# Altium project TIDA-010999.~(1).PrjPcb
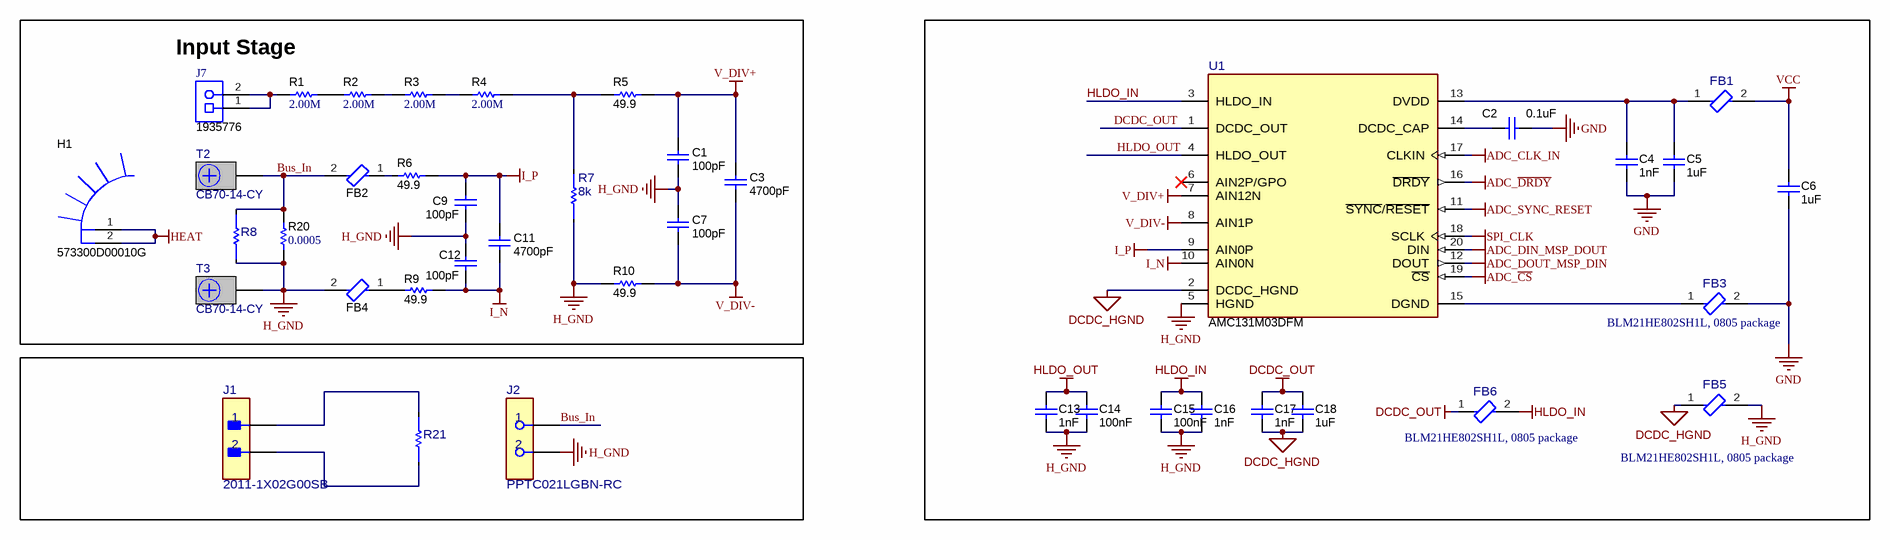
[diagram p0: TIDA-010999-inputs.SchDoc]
CopyrightYear: 2018; PCB_Layout: Who did the Layout?; PCB_Rev: E1; PRJ_Customer: Public Release; PRJ_Engineer: Enter name of project lead; PRJ_Number: XXX###; PRJ_Title: Change in menu Project|Project Options|Parameters; SCH_Rev: E1; TechSupport: http://www.ti.com/support; TID: N/A
3 sheets, 93 parts. Net scope: global (net labels, ports and power ports of the same name join across sheets).
Board file: TIDA-010999.PcbDoc
Sheets:
  TIDA-010999-inputs.SchDoc
  TIDA-010999_Hardware.SchDoc
  Sheet2.SchDoc

## Sheet TIDA-010999-inputs.SchDoc
size 431 x 279 mm; Date: Not shown in title block; ApprovedBy: Not shown in title block; CheckedBy: Not shown in title block; Author: Not shown in title block; CompanyName: Not shown in title block; Engineer: Not shown in title block; Organization: Not shown in title block; Address1: Not shown in title block; Address2: Not shown in title block; Address3: Not shown in title block; Address4: Not shown in title block; DocumentNumber: 2; Revision: Use project parameter SCH_Rev; SheetNumber: 1; SheetTotal: 2; PageSetup: Record=PageOptions¦CenterHorizontal=True¦CenterVertical=True¦PrintScale=1.00¦XCorrection=1.00¦YCorrection=1.00¦PrintKind=0¦BorderSize=5000000¦LeftOffset=0¦BottomOffset=0¦Orientation=2¦PaperLength=1000¦PaperWidth=1000¦Scale=100¦PaperSource=15¦PrintQuality=600¦MediaType=1¦DitherType=10¦PaperKind=Letter¦PrintScaleMode=1

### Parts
C1  ValueDisplayed: 100pF  [0603]  (hidden comment: 885012006057)
C2  value 0.1uF  [0603]  (hidden comment: C1608X7R1H104K080AA)
C3  ValueDisplayed: 4700pF  [0603]  (hidden comment: C0603C472J1GAC7867)
C4  Cap_F: 1nF  [0603]  (hidden comment: C0603C102K5RACTU)
C5  ValueDisplayed: 1uF  [0603]  (hidden comment: C0603C105K3RACTU)
C6  ValueDisplayed: 1uF  [0603]  (hidden comment: C0603C105K3RACTU)
C7  ValueDisplayed: 100pF  [0603]  (hidden comment: 885012006057)
C9  ValueDisplayed: 100pF  [0603]  (hidden comment: 885012006057)
C11  ValueDisplayed: 4700pF  [0603]  (hidden comment: C0603C472J1GAC7867)
C12  ValueDisplayed: 100pF  [0603]  (hidden comment: 885012006057)
C13  Cap_F: 1nF  [0603]  (hidden comment: C0603C102K5RACTU)
C14  Cap_F: 100nF  [0603]  (hidden comment: C1608X7R1H104K080AA)
C15  Cap_F: 100nF  [0603]  (hidden comment: C1608X7R1H104K080AA)
C16  Cap_F: 1nF  [0603]  (hidden comment: C0603C102K5RACTU)
C17  Cap_F: 1nF  [0603]  (hidden comment: C0603C102K5RACTU)
C18  ValueDisplayed: 1uF  [0603]  (hidden comment: C0603C105K3RACTU)
FB1  BLM21HE472SH1L  [FP-BLM21HE472SH1L_0805-MFG]  (value not drawn)
FB2  74269244182  [FP-74269244182_0402-MFG]  (value not drawn)
FB3  BLM21HE472SH1L  [FP-BLM21HE472SH1L_0805-MFG]  (value not drawn)
FB4  74269244182  [FP-74269244182_0402-MFG]  (value not drawn)
FB5  BLM21HE472SH1L  [FP-BLM21HE472SH1L_0805-MFG]  (value not drawn)
FB6  BLM21HE472SH1L  [FP-BLM21HE472SH1L_0805-MFG]  (value not drawn)
H1  573300D00010G  [HEATSINK_573300D00010G]
J1  2011-1X02G00SB  [FP-2011-1X02G00SB_HDR-MFG]
J2  PPTC021LGBN-RC  [FP-PPTC021LGBN-RC_CONN_HDR2-MFG]
J7  1935776  [Phoenix_1935776]
R1  ValueDisplayed: 2.00M  [TNPV1206]  (hidden comment: TNPV12062M00BEEN)
R2  ValueDisplayed: 2.00M  [TNPV1206]  (hidden comment: TNPV12062M00BEEN)
R3  ValueDisplayed: 2.00M  [TNPV1206]  (hidden comment: TNPV12062M00BEEN)
R4  ValueDisplayed: 2.00M  [TNPV1206]  (hidden comment: TNPV12062M00BEEN)
R5  ValueDisplayed: 49.9  [0603]  (hidden comment: CRCW060349R9FKEA)
R6  ValueDisplayed: 49.9  [0603]  (hidden comment: CRCW060349R9FKEA)
R7  8k  [FP-RT0603BRE078KL_0603-MFG]
R8  EBWM2512F1L00S9  [FP-EBWM2512F1L00S9_2512-MFG]  (value not drawn)
R9  ValueDisplayed: 49.9  [0603]  (hidden comment: CRCW060349R9FKEA)
R10  ValueDisplayed: 49.9  [0603]  (hidden comment: CRCW060349R9FKEA)
R20  ValueDisplayed: 0.0005  [WSLF2512L5000]  (hidden comment: WSLF2512L5000FEA)
R21  SBZ-8420-CM2-R00005  [FP-SBZ-8420-CM2-R00005_8420-MFG]  (value not drawn)
T2  CB70-14-CY  [CB70-14-CY]
T3  CB70-14-CY  [CB70-14-CY]
U1  AMC131M03DFM  [DFM0020A-MFG]

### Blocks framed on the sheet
Input Stage: C1 C3 C7 C9 C11 C12 FB2 FB4 H1 J7 R1-R10 R20 T2 T3

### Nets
ADC_~{CS}: U1.19(~{CS})
ADC_CLK_IN: U1.17(CLKIN)
ADC_~{DRDY}: U1.16(~{DRDY})
ADC_DIN_MSP_DOUT: U1.20(DIN)
ADC_DOUT_MSP_DIN: U1.12(DOUT)
ADC_SYNC_RESET: U1.11(~{SYNC}/~{RESET})
DCDC_HGND: C17.2 C18.1 FB5.1 U1.2(DCDC_HGND)
DCDC_OUT: C17.1 C18.2 FB6.1 U1.1(DCDC_OUT)
GND: C2.2 C4.2 C5.1 C6.1 FB3.2
H_GND: C1.2 C7.1 C9.2 C12.1 C13.2 C14.2 C15.2 C16.2 FB4.2 FB5.2 J2.2 R7.1 R8.1 R10.1 R20.1 T3.1 U1.5(HGND)
HEAT: H1.1 H1.2
HLDO_IN: C15.1 C16.1 FB6.2 U1.3(HLDO_IN)
HLDO_OUT: C13.1 C14.1 U1.4(HLDO_OUT)
I_N: C11.2 C12.2 R9.2 U1.10(AIN0N)
I_P: C9.1 C11.1 R6.2 U1.9(AIN0P)
SPI_CLK: U1.18(SCLK)
V_DIV+: C1.1 C3.1 R5.2 U1.7(AIN12N)
V_DIV-: C3.2 C7.2 R10.2 U1.8(AIN1P)
VCC: C6.2 FB1.2
Bus_In: FB2.2 J2.1 R8.2 R20.2 T2.1
NetC2_1: C2.1 U1.14(DCDC_CAP)
NetC4_1: C4.1 C5.2 FB1.1 U1.13(DVDD)
NetFB2_1: FB2.1 R6.1
NetFB3_1: FB3.1 U1.15(DGND)
NetFB4_1: FB4.1 R9.1
NetJ1_1: J1.1 R21.2
NetJ1_2: J1.2 R21.1
NetJ7_1: J7.1 J7.2 R1.1
NetR1_2: R1.2 R2.1
NetR2_2: R2.2 R3.1
NetR3_2: R3.2 R4.1
NetR4_2: R4.2 R5.1 R7.2

Not connected (* = marked no-connect by the designer): U1 6(AIN2P/GPO)*

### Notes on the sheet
- (near FB3) BLM21HE802SH1L, 0805 package
- (near FB6) BLM21HE802SH1L, 0805 package
- (near FB5) BLM21HE802SH1L, 0805 package

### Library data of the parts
C1 C7 C9 C12 = CMP-0006822-4: CAP, CERM, 100 pF, 50 V, +/- 5%, C0G/NP0, 0603; Manufacturer: Wurth Elektronik; TaMin_C: -55°C; Polarized: N; SizeAreaWB_mm2: 4.68; Value1: Unknown; U/M: EA; Value: 100pF; TaMax_C: 125°C; SizeZ_mm: 1; SizeX_mm: 1.6; SizeY_mm: 0.8; Value2: 50V; SizeArea_mm2: 1.28; AEC Category: Q200
C2 = CMP-0007044-5: CAP, CERM, 0.1 uF, 50 V, +/- 10%, X7R, 0603; Manufacturer: TDK; TaMin_C: -55°C; ESR_ohm: 29.6m; Polarized: N; SizeAreaWB_mm2: 4.68; Value1: 0.0296 ohm; U/M: EA; TaMax_C: 125°C; SizeZ_mm: 1; SizeX_mm: 1.6; SizeY_mm: 0.8; Value2: 50V; SizeArea_mm2: 1.28; IRMS_A: 971.99mA; AEC Category: Q200
C3 C11 = CMP-0006941-4: CAP, CERM, 4700 pF, 100 V, +/- 5%, C0G/NP0, 0603; Manufacturer: Kemet; TaMin_C: -55°C; Polarized: N; SizeAreaWB_mm2: 4.68; Value1: Unknown; U/M: EA; Value: 4700pF; TaMax_C: 125°C; SizeZ_mm: 1; SizeX_mm: 1.6; SizeY_mm: 0.8; Value2: 100V; SizeArea_mm2: 1.28; Cap_F: 4.7nF; AEC Category: Q200
C4 C13 C16 C17 = CMP-0006847-4: CAP, CERM, 1000 pF, 50 V, +/- 10%, X7R, 0603; Manufacturer: Kemet; TaMin_C: -55°C; Polarized: N; SizeAreaWB_mm2: 4.68; Value1: Unknown; U/M: EA; Value: 1000pF; TaMax_C: 125°C; SizeZ_mm: 1; SizeX_mm: 1.6; SizeY_mm: 0.8; Value2: 50V; SizeArea_mm2: 1.28; AEC Category: Q200
C5 C6 C18 = CMP-0006867-4: CAP, CERM, 1 uF, 25 V, +/- 10%, X7R, 0603; Manufacturer: Kemet; TaMin_C: -55°C; Polarized: N; SizeAreaWB_mm2: 4.68; Value1: Unknown; U/M: EA; Value: 1uF; TaMax_C: 125°C; SizeZ_mm: 1; SizeX_mm: 1.6; SizeY_mm: 0.8; Value2: 25V; SizeArea_mm2: 1.28; CompType: Capacitor; Cap_F: 1µF; AEC Category: Q200
C14 C15 = CMP-0007044-5: CAP, CERM, 0.1 uF, 50 V, +/- 10%, X7R, 0603; Manufacturer: TDK; TaMin_C: -55°C; ESR_ohm: 29.6m; Polarized: N; SizeAreaWB_mm2: 4.68; Value1: 0.0296 ohm; U/M: EA; Value: 0.1uF; TaMax_C: 125°C; SizeZ_mm: 1; SizeX_mm: 1.6; SizeY_mm: 0.8; Value2: 50V; SizeArea_mm2: 1.28; IRMS_A: 971.99mA; AEC Category: Q200
FB1 FB3 FB5 FB6 = CMP-0037616-1: 4.7 kOhms @ 100 MHz 1 Signal Line Ferrite Bead 0805 (2012 Metric) 850mA 400mOhm; Manufacturer: Murata; DCR_ohm: 0.4; SizeZ_mm: 1.45mm; AEC Grade: Grade 1; AEC Qualified: Yes; Impedance At Frequency: 4700Ω @ 100MHz
FB2 FB4 = CMP-0091663-1: 1.8 kOhms @ 100MHz 1 Power, Signal Line Ferrite Bead 0402 (1005 Metric) 210mA 2.1Ohm; Manufacturer: Wurth Electronics; SizeZ_mm: 0.55mm; AEC Qualified: No; DCR_ohm: 2.1; Tolerance_%: 25%; Test Frequency: 1GHz; Impedance At Frequency: 1800Ω @ 100MHz
H1 = CMP-0004011-1: Heatsink, DDPAK/TO-263, SMT; Manufacturer: Aavid
J1 = CMP-0092598-1: Connector Header Through Hole 2 position 0.100" (2.54mm); Manufacturer: Oupiin; Row_Count: 1; SizeZ_mm: 9.1mm; Conn Orientation: Straight; AEC Qualified: No; Current_A: 3A; ContactFinish: Gold,Nickel; Conn Gender: Male; Voltage_V: 150V
J2 = CMP-0122186-1: 2 Position Header Connector 0.100" (2.54mm) Through Hole, Right Angle Tin; Manufacturer: Sullins; ContactFinish: Tin,Nickel; Current_A: 3A; Row_Count: 1; Voltage_V: 250V; AEC Qualified: No; Conn Gender: Female; Is Female: yes; SizeZ_mm: 2.74mm
J7 = CMP-0055506-1: Terminal Block, 2x1, 5mm, Green, TH; Manufacturer: Phoenix Contact; CNHeader: FALSE; Green_Lifecycle: Not Set; Gender: Female; Green_REACh: Incomplete; Row_Count: 1; Pitch_mm: 5; CT: TRUE
R1-R4 = CMP-0018810-2: RES, 2.00 M, 0.1%, 1 W, 1206; Manufacturer: Vishay Draloric; Power_W: 1W; TempCo: 25 ppm/C; Value_Code: 2M00; U/M: EA; Value: 2.00Meg; EIA_Code: E192; Res_ohm: 2M; SizeX_mm: 3.2; SizeY_mm: 1.6; SizeZ_mm: 0.65; SizeArea_mm2: 5.12; AEC Qualified: N; VDC_V: 700V; AEC Category: Q200
R5 R10 = CMP-0022448-2: RES, 49.9, 1%, 0.1 W, 0603; Manufacturer: Vishay-Dale; Power_W: 100mW; TempCo: 100 ppm/C; Value_Code: 49R9; U/M: EA; Value: 49.9; EIA_Code: E96; SizeX_mm: 1.6; SizeY_mm: 0.8; SizeZ_mm: 1; Value2: 0.1W; SizeArea_mm2: 1.28; VDC_V: 75V; AEC Category: Q200
R6 R9 = CMP-0022448-4: RES, 49.9, 1%, 0.1 W, AEC-Q200 Grade 0, 0603; Manufacturer: Vishay-Dale; Power_W: 100mW; TempCo: 100 ppm/C; Value_Code: 49R9; Value: 49.9; EIA_Code: E96; SizeX_mm: 1.6; SizeY_mm: 0.8; SizeZ_mm: 1; Value2: 0.1W; SizeArea_mm2: 1.28; AEC Qualified: Y; VDC_V: 75V; AEC Category: Q200; AEC Grade: 0
R7 = CMP-0122747-1: 8 kOhms ±0.1% 0.1W, 1/10W Chip Resistor 0603 (1608 Metric) Thin Film; Manufacturer: Yageo; PartNumber: RT0603BRE078KL; AEC Qualified: No; Power_W: 100mW; SizeZ_mm: 0.55mm; TempCo: 50ppm/°C; VDC_V: 75V
R8 = CMP-0127357-1: 1 mOhms ±1% 6W Chip Resistor 2512 (6332 Metric) Automotive AEC-Q200, Current Sense Metal Element; Manufacturer: RESI; AEC Grade: Grade 0; AEC Qualified: Yes; Res_ohm: 1m; SizeZ_mm: 1.1mm; TempCo: 200ppm/°C; Value: 1m
R20 = CMP-0086033-1: RES, 0.0005, 1%, 6 W, AEC-Q200 Grade 0, 6.35x3.02mm; Manufacturer: Vishay-Dale; SizeArea_mm2: 19.177; Value2: 6W; SizeY_mm: 3.02; Value: 0.0005; AEC Qualified: Y; SizeX_mm: 6.35; AEC Category: Q200; Res_ohm: 500µ; TempCo: 200 ppm/C; SizeAreaWB_mm2: 41.917; Value_Code: L5000; SizeZ_mm: 1.22; AEC Grade: 0
R21 = CMP-0127450-1: Low Ohmic EB Welded Precision Resistor 0.05mOhm 36W AEC-Q200; Manufacturer: Shivalik Bimetal Controls; AEC Grade: Grade 0; AEC Qualified: Yes; Res_ohm: 50µ; SizeZ_mm: 3.1mm; TempCo: 100ppm/°C; Value: 50µ
T2 T3 = CMP-0055443-2: Terminal 90A Lug; Manufacturer: Panduit; Green_Lifecycle: Not Set; Cert_CULUS: Y; Green_REACh: Incomplete; Voltage_V: 600V; CompType: Screw Terminal; ContactFinish: Copper
U1 = CMP-0093943-1: 3-Channel, Simultaneously-Sampling, 24-Bit, Reinforced Isolated DeltaSigma ADC With Integrated DC/DC Converter; Manufacturer: Texas Instruments; Interface: SPI; TaMax_C: +125°C; Standoff Height: 0.1mm; Resolution: 24bits; Max Supply Voltage: 5.5V; Data Polarity: Differential; Min Supply Voltage: 3V; TJmax_C: +150°C; Number Of Channels: 3; Sampling Rate: 32ksps; TaMin_C: -40°C; SizeZ_mm: 3.55mm; AEC Qualified: No

## Sheet TIDA-010999_Hardware.SchDoc
size 431 x 279 mm; Date: Not shown in title block; ApprovedBy: Not shown in title block; CheckedBy: Not shown in title block; Author: Not shown in title block; CompanyName: Not shown in title block; Engineer: Not shown in title block; Organization: Not shown in title block; Address1: Not shown in title block; Address2: Not shown in title block; Address3: Not shown in title block; Address4: Not shown in title block; DocumentNumber: 3; Revision: Use project parameter SCH_Rev; SheetNumber: 5; SheetTotal: 5; PageSetup: Record=PageOptions¦CenterHorizontal=True¦CenterVertical=True¦PrintScale=1.00¦XCorrection=1.00¦YCorrection=1.00¦PrintKind=0¦BorderSize=5000000¦LeftOffset=0¦BottomOffset=0¦Orientation=2¦PaperLength=1000¦PaperWidth=1000¦Scale=100¦PaperSource=15¦PrintQuality=600¦MediaType=1¦DitherType=10¦PaperKind=Letter¦PrintScaleMode=1
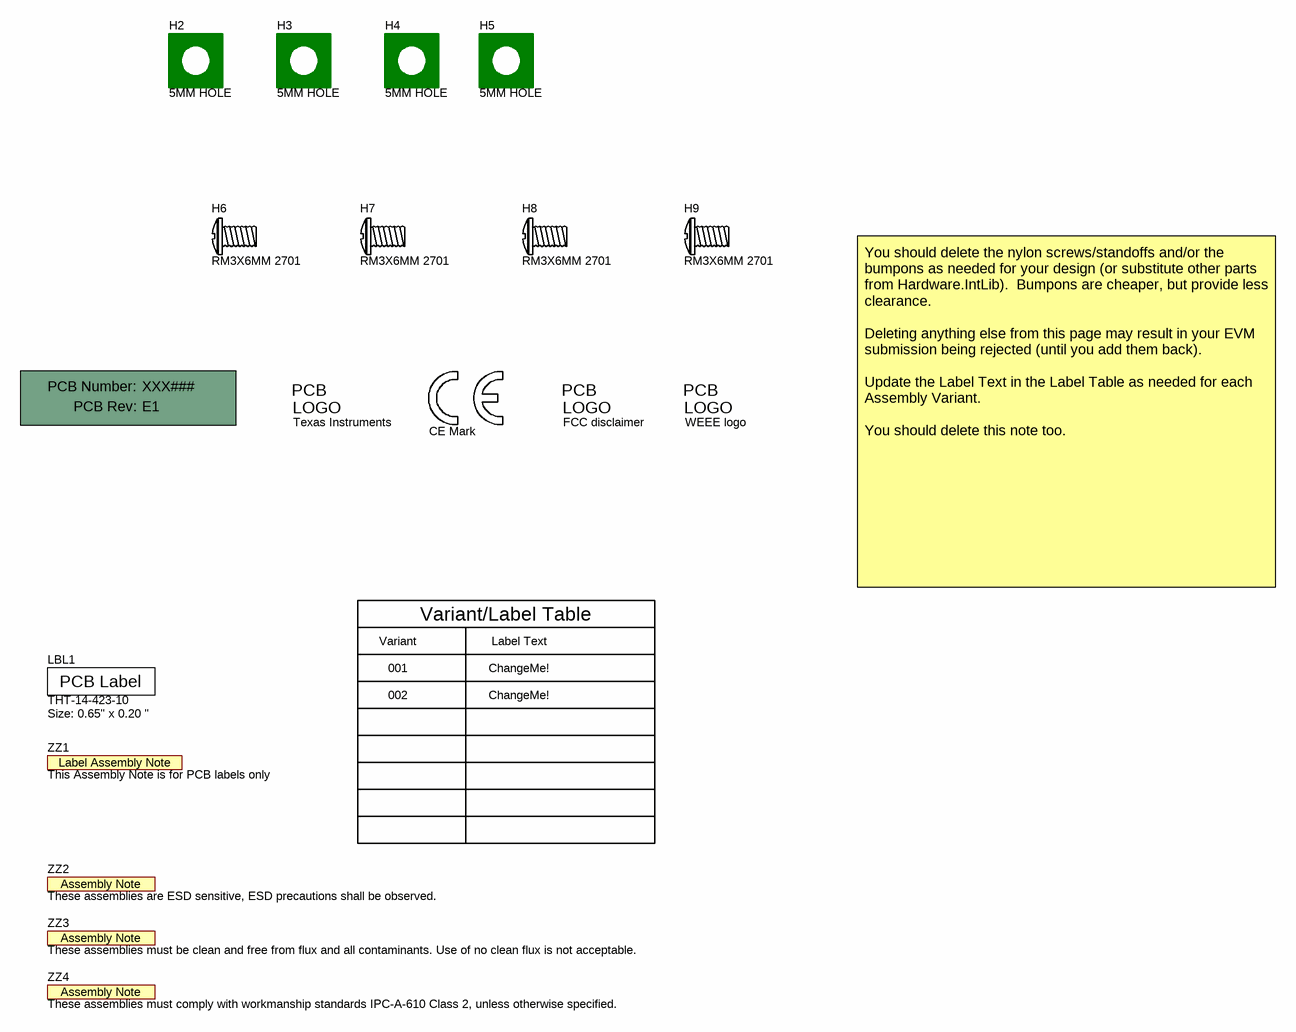
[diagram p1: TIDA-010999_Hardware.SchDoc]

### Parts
!PCB  Printed Circuit Board  (value not drawn)  (mechanical)
H2  5MM HOLE  [5MM_HOLE]
H3  5MM HOLE  [5MM_HOLE]
H4  5MM HOLE  [5MM_HOLE]
H5  5MM HOLE  [5MM_HOLE]
H6  RM3X6MM 2701  (mechanical)
H7  RM3X6MM 2701  (mechanical)
H8  RM3X6MM 2701  (mechanical)
H9  RM3X6MM 2701  (mechanical)
LBL1  THT-14-423-10  Note: Size: 0.65" x 0.20 "  [Label_650x200]
Logo1  Texas Instruments  [TI_Stacked_Overlay_Small]  (no BOM)
Logo2  CE Mark  [CE_Mark_5mm]  (no BOM)
Logo3  FCC disclaimer  [FCC_disclaimer]  (no BOM)
Logo4  WEEE logo  [WEEE_Minimum]  (no BOM)
ZZ1  This Assembly Note is for PCB labels only  [AssemblyNoteLabel]  (no BOM)
ZZ2  These assemblies are ESD sensitive, ESD precautions shall be observed.  [AssemblyNote]  (no BOM)
ZZ3  These assemblies must be clean and free from flux and all contaminants. Use of no clean flux is not acceptable.  [AssemblyNote]  (no BOM)
ZZ4  These assemblies must comply with workmanship standards IPC-A-610 Class 2, unless otherwise specified.  [AssemblyNote]  (no BOM)

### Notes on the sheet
- Variant
- Variant/Label Table
- Label Text
- You should delete the nylon screws/standoffs and/or the bumpons as needed for your design (or substitute other parts from Hardware.IntLib).  Bumpons are cheaper, but provide less clearance.
  Deleting anything else from this page may result in your EVM submission being rejected (until you add them back).
  Update the Label Text in the Label Table as needed for each Assembly Variant.
  You should delete this note too.
- 001
- 002
- ChangeMe!

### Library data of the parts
!PCB = CMP-0003618-2: Manufacturer: Any; PartNumber: XXX###
H2-H5 = CMP-0079337-1: 5 mm PCB Hole; Manufacturer: Any; CompType: Pad
H6-H9 = CMP-0077936-1: MACHINE SCREW PAN PHILLIPS M3; Manufacturer: APM HEXSEAL; CompType: Standoff
LBL1 = CMP-0003625-1: Thermal Transfer Printable Labels, 0.650" W x 0.200" H - 10,000 per roll; Manufacturer: Brady; CompType: Label
Logo1 = CMP-0074838-1: Texas Instrument Corporate Signature; SymbolCreator: a0412235; Lib Reference: TI_Logo; Library Reference: Logo
Logo2 = CMP-0074844-1: SymbolCreator: a0412235
Logo3 = CMP-0074847-1: FCC_disclaimer; Library Reference: Logo
Logo4 = CMP-0074769-1
ZZ1 = CMP-0003616-3
ZZ2 = CMP-0077236-1
ZZ3 = CMP-0077237-1
ZZ4 = CMP-0077238-1

## Sheet Sheet2.SchDoc
size 431 x 279 mm; Date: Not shown in title block; ApprovedBy: Not shown in title block; CheckedBy: Not shown in title block; Author: Not shown in title block; CompanyName: Not shown in title block; Engineer: Not shown in title block; Organization: Not shown in title block; Address1: Not shown in title block; Address2: Not shown in title block; Address3: Not shown in title block; Address4: Not shown in title block; DocumentNumber: 1; Revision: Use project parameter SCH_Rev; SheetNumber: 2; SheetTotal: 2; PageSetup: Record=PageOptions¦CenterHorizontal=True¦CenterVertical=True¦PrintScale=1.00¦XCorrection=1.00¦YCorrection=1.00¦PrintKind=0¦BorderSize=5000000¦LeftOffset=0¦BottomOffset=0¦Orientation=2¦PaperLength=1000¦PaperWidth=1000¦Scale=100¦PaperSource=15¦PrintQuality=600¦MediaType=1¦DitherType=10¦PaperKind=Letter¦PrintScaleMode=1
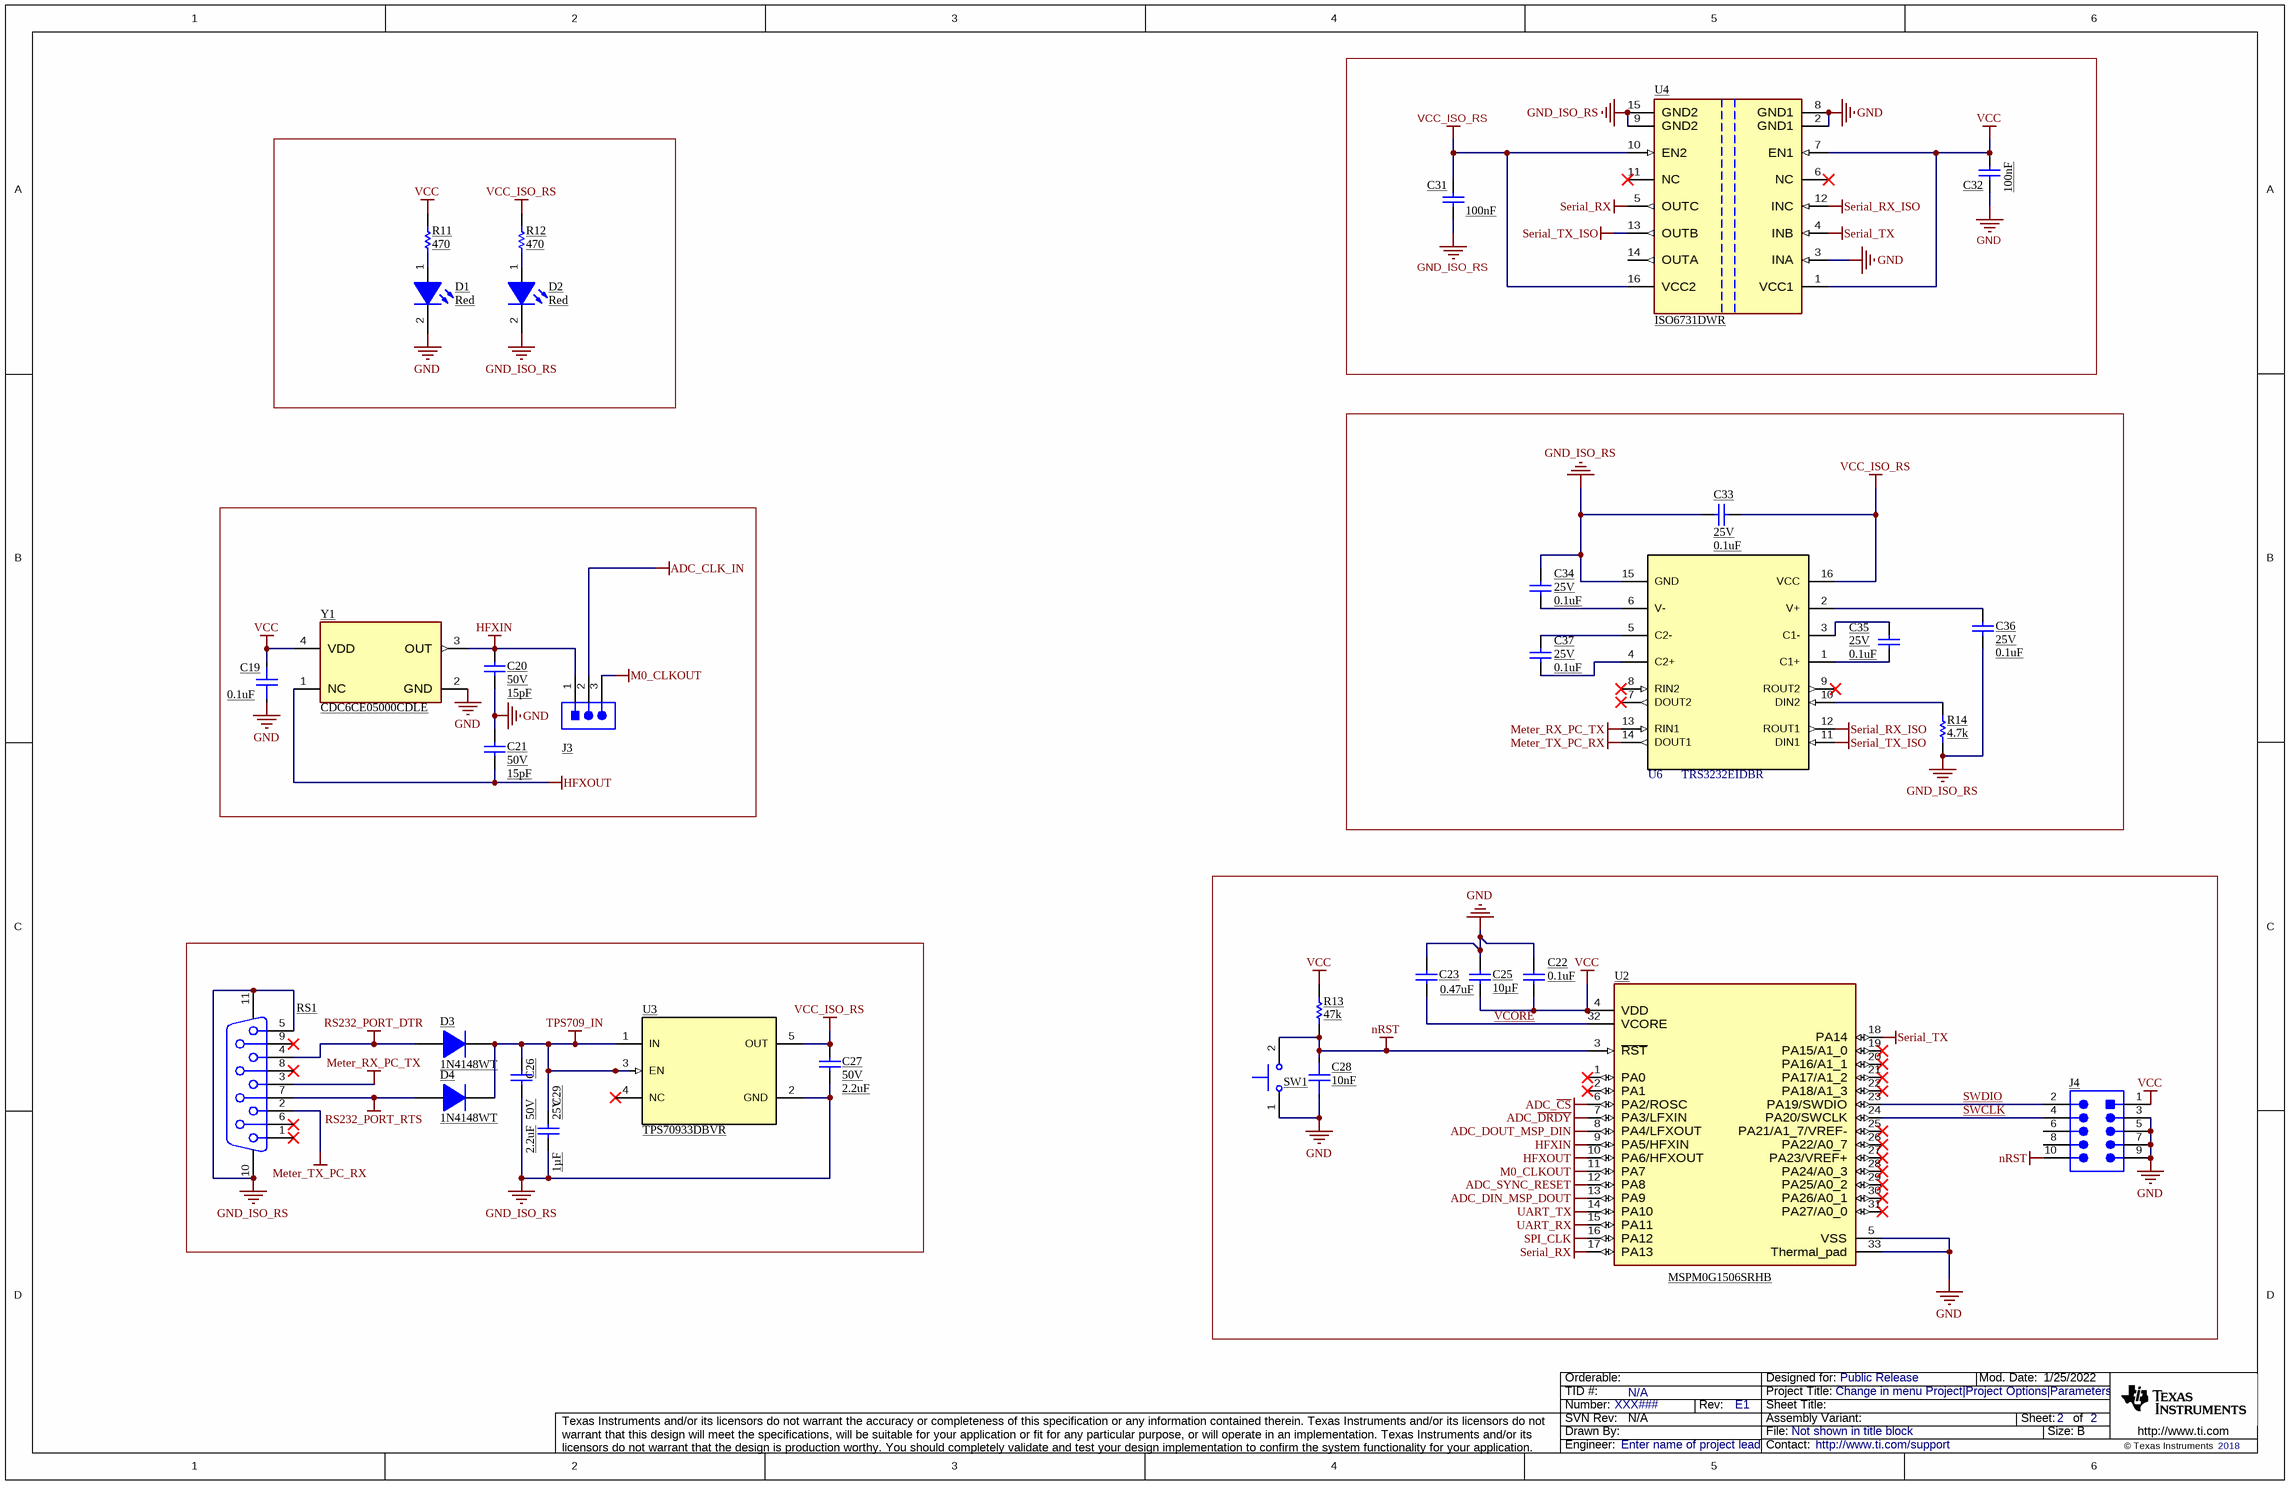
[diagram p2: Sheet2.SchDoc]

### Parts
C19  ValueDisplayed: 0.1uF  [FP-885012205018_0402-MFG]  (hidden comment: 885012205018)
C20  VDC_V: 50V  ValueDisplayed: 15pF  [0402]  (hidden comment: GRM1555C1H150JA01D)
C21  VDC_V: 50V  ValueDisplayed: 15pF  [0402]  (hidden comment: GRM1555C1H150JA01D)
C22  ValueDisplayed: 0.1uF  [0603]  (hidden comment: CGA3E2X8R1E104K080AA)
C23  ValueDisplayed: 0.47uF  [0603]  (hidden comment: GRM188R61A474KA61D)
C25  ValueDisplayed: 10µF  [0603]  (hidden comment: GRM188R61A106KAALD)
C26  VDC_V: 50V  ValueDisplayed: 2.2uF  [0603]  (hidden comment: GRT188R61H225KE13D)
C27  VDC_V: 50V  ValueDisplayed: 2.2uF  [0603]  (hidden comment: GRT188R61H225KE13D)
C28  ValueDisplayed: 10nF  [FP-885012205050_0402-MFG]  (hidden comment: 885012205050)
C29  VDC_V: 25V  ValueDisplayed: 1µF  [0603]  (hidden comment: CGA3E1X7R1E105M080AC)
C31  Cap_F: 100nF  [0603]  (hidden comment: C0603X104K3RACTU)
C32  Cap_F: 100nF  [0603]  (hidden comment: C0603X104K3RACTU)
C33  VDC_V: 25V  ValueDisplayed: 0.1uF  [0603]  (hidden comment: CGA3E2X8R1E104K080AA)
C34  VDC_V: 25V  ValueDisplayed: 0.1uF  [0603]  (hidden comment: CGA3E2X8R1E104K080AA)
C35  VDC_V: 25V  ValueDisplayed: 0.1uF  [0603]  (hidden comment: CGA3E2X8R1E104K080AA)
C36  VDC_V: 25V  ValueDisplayed: 0.1uF  [0603]  (hidden comment: CGA3E2X8R1E104K080AA)
C37  VDC_V: 25V  ValueDisplayed: 0.1uF  [0603]  (hidden comment: CGA3E2X8R1E104K080AA)
D1  value Red  [CMD17-21_Red]  (hidden comment: CMD17-21SRC/TR8)
D2  value Red  [CMD17-21_Red]  (hidden comment: CMD17-21SRC/TR8)
D3  1N4148WT  [Fairchild_SOD-523F]
D4  1N4148WT  [Fairchild_SOD-523F]
J3  22284030  [Molex_0022284030]  (value not drawn)
J4  FTSH-105-01-L-DV-K  [Samtec_FTSH-105-01-x-DV-K]  (value not drawn)
R11  ValueDisplayed: 470  [0402]  (hidden comment: RC0402FR-07470RL)
R12  ValueDisplayed: 470  [0402]  (hidden comment: RC0402FR-07470RL)
R13  ValueDisplayed: 47k  [0402]  (hidden comment: CRCW040247K0JNED)
R14  ValueDisplayed: 4.7k  [0603]  (hidden comment: CRCW06034K70JNEA)
RS1  2-5747706-0  [TE_2-5747706-0]  (value not drawn)
SW1  TL1015AF160QG  [SW_TL1015AF160QG]  (value not drawn)
U2  MSPM0G1506SRHB  [RHB0032N-MFG]
U3  TPS70933DBVR  [DBV0005A_N]
U4  ISO6731DWR  [DW0016A-MFG]
U6  TRS3232EIDBR  [DB0016A_L]
Y1  PartNumber: CDC6CE05000CDLE  [DLE0004A-MFG]  (hidden comment: CDC6CE008192ADLE)

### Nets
ADC_~{CS}: U2.6(PA2/ROSC)
ADC_CLK_IN: J3.2
ADC_~{DRDY}: U2.7(PA3/LFXIN)
ADC_DIN_MSP_DOUT: U2.13(PA9)
ADC_DOUT_MSP_DIN: U2.8(PA4/LFXOUT)
ADC_SYNC_RESET: U2.12(PA8)
GND: C19.1 C20.2 C21.1 C22.1 C23.1 C25.1 C28.1 C32.2 D1.2(K) J4.3 J4.5 J4.7 J4.9 SW1.1 U2.5(VSS) U2.33(Thermal_pad) U4.2(GND1) U4.3(INA) U4.8(GND1) Y1.2(GND)
GND_ISO_RS: C26.2 C27.2 C29.2 C31.2 C33.1 C34.1 C36.1 D2.2(K) R14.1 RS1.5 RS1.10 RS1.11 U3.2(GND) U4.9(GND2) U4.15(GND2) U6.15(GND)
HFXIN: C20.1 J3.1 U2.9(PA5/HFXIN) Y1.3(OUT)
HFXOUT: C21.2 U2.10(PA6/HFXOUT) Y1.1(NC)
M0_CLKOUT: J3.3 U2.11(PA7)
Meter_RX_PC_TX: RS1.3 U6.13(RIN1)
Meter_TX_PC_RX: RS1.2 U6.14(DOUT1)
nRST: C28.2 J4.10 R13.1 SW1.2 U2.3(~{RST})
RS232_PORT_DTR: D3.2(A) RS1.4
RS232_PORT_RTS: D4.2(A) RS1.7
Serial_RX: U2.17(PA13) U4.5(OUTC)
Serial_RX_ISO: U4.12(INC) U6.12(ROUT1)
Serial_TX: U2.18(PA14) U4.4(INB)
Serial_TX_ISO: U4.13(OUTB) U6.11(DIN1)
SPI_CLK: U2.16(PA12)
TPS709_IN: C26.1 C29.1 D3.1(K) D4.1(K) U3.1(IN) U3.3(EN)
UART_RX: U2.15(PA11)
UART_TX: U2.14(PA10)
VCC: C19.2 C22.2 C25.2 C32.1 J4.1 R11.2 R13.2 U2.4(VDD) U4.1(VCC1) U4.7(EN1) Y1.4(VDD)
VCC_ISO_RS: C27.1 C31.1 C33.2 R12.2 U3.5(OUT) U4.10(EN2) U4.16(VCC2) U6.16(VCC)
SWCLK: J4.4 U2.24(PA20/SWCLK)
SWDIO: J4.2 U2.23(PA19/SWDIO)
VCORE: C23.2 U2.32(VCORE)
NetC34_2: C34.2 U6.6(V-)
NetC35_1: C35.1 U6.3(C1-)
NetC35_2: C35.2 U6.1(C1+)
NetC36_2: C36.2 U6.2(V+)
NetC37_1: C37.1 U6.5(C2-)
NetC37_2: C37.2 U6.4(C2+)
NetD1_1: D1.1(A) R11.1
NetD2_1: D2.1(A) R12.1
NetR14_2: R14.2 U6.10(DIN2)

Not connected (* = marked no-connect by the designer): J4 6 8; RS1 1* 6* 8* 9*; U2 1(PA0)* 2(PA1)* 19(PA15/A1_0)* 20(PA16/A1_1)* 21(PA17/A1_2)* 22(PA18/A1_3)* 25(PA21/A1_7/VREF-)* 26(PA22/A0_7)* 27(PA23/VREF+)* 28(PA24/A0_3)* 29(PA25/A0_2)* 30(PA26/A0_1)* 31(PA27/A0_0)*; U3 4(NC)*; U4 6(NC)* 11(NC)* 14(OUTA); U6 7(DOUT2)* 8(RIN2)* 9(ROUT2)*

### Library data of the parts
C19 = CMP-0090362-1: 0.1µF ±10% 10V Ceramic Capacitor X7R 0402 (1005 Metric); Manufacturer: Wurth Electronics; AEC Qualified: No; Value: 100nF; SizeZ_mm: 0.55mm; TempCo: 15%
C20 C21 = CMP-0006420-2: CAP, CERM, 15 pF, 50 V, +/- 5%, C0G/NP0, 0402; Manufacturer: MuRata; TaMin_C: -55°C; Polarized: N; SizeAreaWB_mm2: 3; Value1: Unknown; U/M: EA; Value: 15pF; TaMax_C: 125°C; SizeZ_mm: 0.6; SizeX_mm: 1; SizeY_mm: 0.5; AEC Category: Q200
C22 = CMP-0007090-4: CAP, CERM, 0.1 uF, 25 V, +/- 10%, X8R, AEC-Q200 Grade 0, 0603; Manufacturer: TDK; TaMin_C: -55°C; Polarized: N; SizeAreaWB_mm2: 4.68; Value1: Unknown; U/M: EA; Value: 0.1uF; TaMax_C: 150°C; SizeZ_mm: 1; SizeX_mm: 1.6; SizeY_mm: 0.8; Value2: 25V; SizeArea_mm2: 1.28; AEC Qualified: Y; Cap_F: 100nF; AEC Grade: 0; AEC Category: Q200
C23 = CMP-0007328-5: CAP, CERM, 0.47 uF, 10 V, +/- 10%, X5R, 0603; Manufacturer: MuRata; TaMin_C: -55°C; Polarized: N; SizeAreaWB_mm2: 4.68; Value1: Unknown; U/M: EA; Value: 0.47uF; TaMax_C: 85°C; SizeZ_mm: 1; SizeX_mm: 1.6; SizeY_mm: 0.8; Value2: 10V; SizeArea_mm2: 1.28; Cap_F: 470nF; AEC Category: Q200
C25 = CMP-0086193-1: CAP, CERM, 10 µF, 10 V,+/- 10%, X5R, 0603; Manufacturer: MuRata; SizeArea_mm2: 1.28; SizeY_mm: 0.8; TaMax_C: 85°C; TaMin_C: -55°C; VDC_V: 10V; Polarized: N; SizeAreaWB_mm2: 4.68; SizeZ_mm: 1; SizeX_mm: 1.6; AEC Category: Q200; U/M: EA; Value: 10uF
C26 C27 = CMP-0007502-5: CAP, CERM, 2.2 uF, 50 V, +/- 10%, X5R, AEC-Q200 Grade 3, 0603; Manufacturer: MuRata; TaMin_C: -55°C; Polarized: N; SizeAreaWB_mm2: 4.68; Value1: Unknown; U/M: EA; Value: 2.2uF; TaMax_C: 85°C; SizeZ_mm: 1; SizeX_mm: 1.6; SizeY_mm: 0.8; SizeArea_mm2: 1.28; CompType: Capacitor; AEC Qualified: Y; Cap_F: 2.2µF; AEC Grade: 3; AEC Category: Q200
C28 = CMP-0090363-1: 10000pF ±10% 25V Ceramic Capacitor X7R 0402 (1005 Metric); Manufacturer: Wurth Electronics; SizeZ_mm: 0.55mm; AEC Qualified: No; Value: 10nF; TempCo: 15%
C29 = CMP-0082113-1: CAP, CERM, 1 µF, 25 V,+/- 20%, X7R, AEC-Q200 Grade 1, 0603; Manufacturer: TDK; SizeAreaWB_mm2: 4.68; SizeArea_mm2: 1.28; AEC Qualified: Y; AEC Category: Q200; Value: 1uF; TaMax_C: 125°C; SizeZ_mm: 1; Polarized: N; TaMin_C: -55°C; SizeY_mm: 0.8; U/M: EA; SizeX_mm: 1.6
C31 C32 = CMP-0006979-5: CAP, CERM, 0.1 uF, 25 V, +/- 10%, X7R, 0603; Manufacturer: Kemet; TaMin_C: -55°C; Polarized: N; SizeAreaWB_mm2: 4.68; Value1: Unknown; U/M: EA; Value: 0.1uF; TaMax_C: 125°C; SizeZ_mm: 1; SizeX_mm: 1.6; SizeY_mm: 0.8; Value2: 25V; SizeArea_mm2: 1.28; AEC Category: Q200
C33-C37 = CMP-0007090-4: CAP, CERM, 0.1 uF, 25 V, +/- 10%, X8R, AEC-Q200 Grade 0, 0603; Manufacturer: TDK; TaMin_C: -55°C; Polarized: N; SizeAreaWB_mm2: 4.68; Value1: Unknown; U/M: EA; Value: 0.1uF; TaMax_C: 150°C; SizeZ_mm: 1; SizeX_mm: 1.6; SizeY_mm: 0.8; SizeArea_mm2: 1.28; AEC Qualified: Y; Cap_F: 100nF; AEC Grade: 0; AEC Category: Q200
D1 D2 = CMP-0084855-1: LED, Red, SMD; Manufacturer: Visual Communications Company, LLC; SizeX_mm: 2; SizeArea_mm2: 2.5; SizeAreaWB_mm2: 6.75; Angle: 140; Value2: 1.7V; Ir_A: 100µA; Value1: 0.1W; SizeY_mm: 1.25; Io_A: 20mA; Tjmax_C: 85°C; Power_TotalModule: 100mW; SizeZ_mm: 1.2; Vr_V: 5V
D3 D4 = CMP-0076982-2: Diode, Switching, 75 V, 0.3 A, SOD-523F; Manufacturer: Fairchild Semiconductor; TJmax_C: 150°C; AEC Category: Q101; SizeX_mm: 1.6; Value: 75V; Io_A: 300mA; Value1: 0.3A; Green_REACh: Incomplete; SizeZ_mm: 0.7; Green_Lifecycle: Not Set; SizeArea_mm2: 1.28; SizeAreaWB_mm2: 4.68; SizeY_mm: 0.8
J3 = CMP-0078237-1: Header, 2.54mm, 3x1, Tin, TH; Manufacturer: Molex; Pitch_mm: 2.54; Gender: Male; Cert_CSA: Y; Current_A: 4A; Voltage_V: 500V; Shrouded: N; Row_Count: 1
J4 = CMP-0075634-1: Header(Shrouded), 1.27mm, 5x2, Gold, SMT; Manufacturer: Samtec; Pitch_mm: 1.27; Gender: Male; Cert_CSA: Y; Current_A: 3.3A; CT: False; Row_Count: 2
R11 R12 = CMP-0026736-1: RES, 470, 1%, 0.063 W, 0402; Manufacturer: Yageo America; Power_W: 63mW; TempCo: 100 ppm/C; Value_Code: 470R; U/M: EA; Value: 470; SizeX_mm: 1; SizeY_mm: 0.5; SizeZ_mm: 0.6; Value2: 0.063W; AEC Qualified: N; VDC_V: 50V; AEC Category: Q200
R13 = CMP-0026935-3: RES, 47 k, 5%, 0.063 W, AEC-Q200 Grade 0, 0402; Manufacturer: Vishay-Dale; Power_W: 63mW; TempCo: 200 ppm/C; Value_Code: 47k0; Value: 47k; EIA_Code: E24; SizeX_mm: 1; SizeY_mm: 0.5; SizeZ_mm: 0.6; Value2: 0.063W; AEC Qualified: Y; VDC_V: 50V; AEC Category: Q200; AEC Grade: 0
R14 = CMP-0025817-4: RES, 4.7 k, 5%, 0.1 W, AEC-Q200 Grade 0, 0603; Manufacturer: Vishay-Dale; Power_W: 100mW; TempCo: 200 ppm/C; Value_Code: 4k70; Value: 4.7k; EIA_Code: E24; SizeX_mm: 1.6; SizeY_mm: 0.8; SizeZ_mm: 1; Value2: 0.1W; SizeArea_mm2: 1.28; AEC Qualified: Y; VDC_V: 75V; AEC Category: Q200; AEC Grade: 0
RS1 = CMP-0079577-1: Receptacle, D-SUB-9, 2.74mm, Gold, TH; Manufacturer: TE Connectivity; Gender: Female; Cert_UL: Y; Voltage_V: 125V; Current_A: 6A; Row_Count: 2; CompType: D-Sub
SW1 = CMP-0002143-2: Switch, Tactile, SPST-NO, 0.05A, 12V, SMT; Manufacturer: E-Switch; CurrentRating_mA: 50A; PositionCount: 1; SwitchFunction: Off-Mom
U2 = CMP-0094692-4: Mixed-Signal Microcontrollers; Manufacturer: Texas Instruments; Frequency_Fixed: 80MHz; Number Of Timers/Counters: 7; Number Of Cores: 1; AEC Category: Q200; Data Bus Width: 32bits; Standoff Height: 0mm; Memory Type: FLASH; Number Of Uart Channels: 4; Memory Size: 64KBytes; TaMin_C: -40°C; Number Of I2C Channels: 2; Max Supply Voltage: 3.6V; SizeZ_mm: 0.9mm; CompType: IC; Interface: I2C,SPI,UART,LIN,IrDA,SMBus; Min Supply Voltage: 1.35V; AEC Qualified: No; Core Architecture: ARM Cortex-M0+; Number Of Adc Channels: 10; Ram Size: 32KBytes; Number Of I/Os: 28; TaMax_C: +105°C
U3 = CMP-0073793-1: 150-mA, 30-V, Ultra-Low IQ, Wide Input Low-Dropout Regulator with Reverse Current Protection, DBV0005A (SOT-23-5); Alternate PartNumber: TPS70933DBVT; Alternate Manufacturer: Texas Instruments; Green_Lifecycle: Active; SizeAreaWB_mm2: 14.82; Green_REACh: Passed; U/M: EA; SizeZ_mm: 1.45; SizeX_mm: 2.8; SizeY_mm: 2.9; SizeArea_mm2: 8.12; CompType: IC
U4 = CMP-0094636-1: Manufacturer: Texas Instruments; Min Supply Voltage: 1.71V; TJmax_C: +150°C; Max Supply Voltage: 5.5V; Standoff Height: 0.1mm; TaMax_C: +125°C; SizeZ_mm: 2.65mm; Interface: SPI,CAN,RS-232,RS-485; TaMin_C: -40°C; AEC Qualified: No
U6 = CMP-0044119-1: 3-V to 5.5-V Multichannel RS-232 Line Driver / Receiver with ±15-kV IEC ESD Protection, -40 to 85 degC, 16-Pin SSOP (DB), Green (RoHS & no Sb/Br); ESD HBM(kV): +/-15; Receivers Per Package: 2; Single Supply: TRUE; ICC(Max)(mA): 1; Supply Voltage(s)(V): 3.3 or 5.0
Y1 = CMP-0094615-2: Crystal replacement: Ultra-low Power LVCMOS Oscillator 4-pin, VSON 3.2 x 2.5 x 0.9mm; Manufacturer: Texas Instruments; AEC Qualified: No; Standoff Height: 0mm; Min Supply Voltage: 2.375V; TaMin_C: -40°C; Load Capacitance: 15pF; Frequency Stability: 20ppm; AEC Category: Q200; Frequency_Fixed: 50MHz; CompType: IC; SizeZ_mm: 1mm; Max Supply Voltage: 3.465V; TJmax_C: +135°C; TaMax_C: +105°C; Max Supply Current: 4mA

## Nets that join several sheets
ADC_~{CS}: TIDA-010999-inputs (U1.19), Sheet2 (U2.6)
ADC_CLK_IN: TIDA-010999-inputs (U1.17), Sheet2 (J3.2)
ADC_~{DRDY}: TIDA-010999-inputs (U1.16), Sheet2 (U2.7)
ADC_DIN_MSP_DOUT: TIDA-010999-inputs (U1.20), Sheet2 (U2.13)
ADC_DOUT_MSP_DIN: TIDA-010999-inputs (U1.12), Sheet2 (U2.8)
ADC_SYNC_RESET: TIDA-010999-inputs (U1.11), Sheet2 (U2.12)
GND: TIDA-010999-inputs (5 pins), Sheet2 (20 pins)
SPI_CLK: TIDA-010999-inputs (U1.18), Sheet2 (U2.16)
VCC: TIDA-010999-inputs (C6.2 FB1.2), Sheet2 (11 pins)

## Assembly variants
001: all parts fitted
